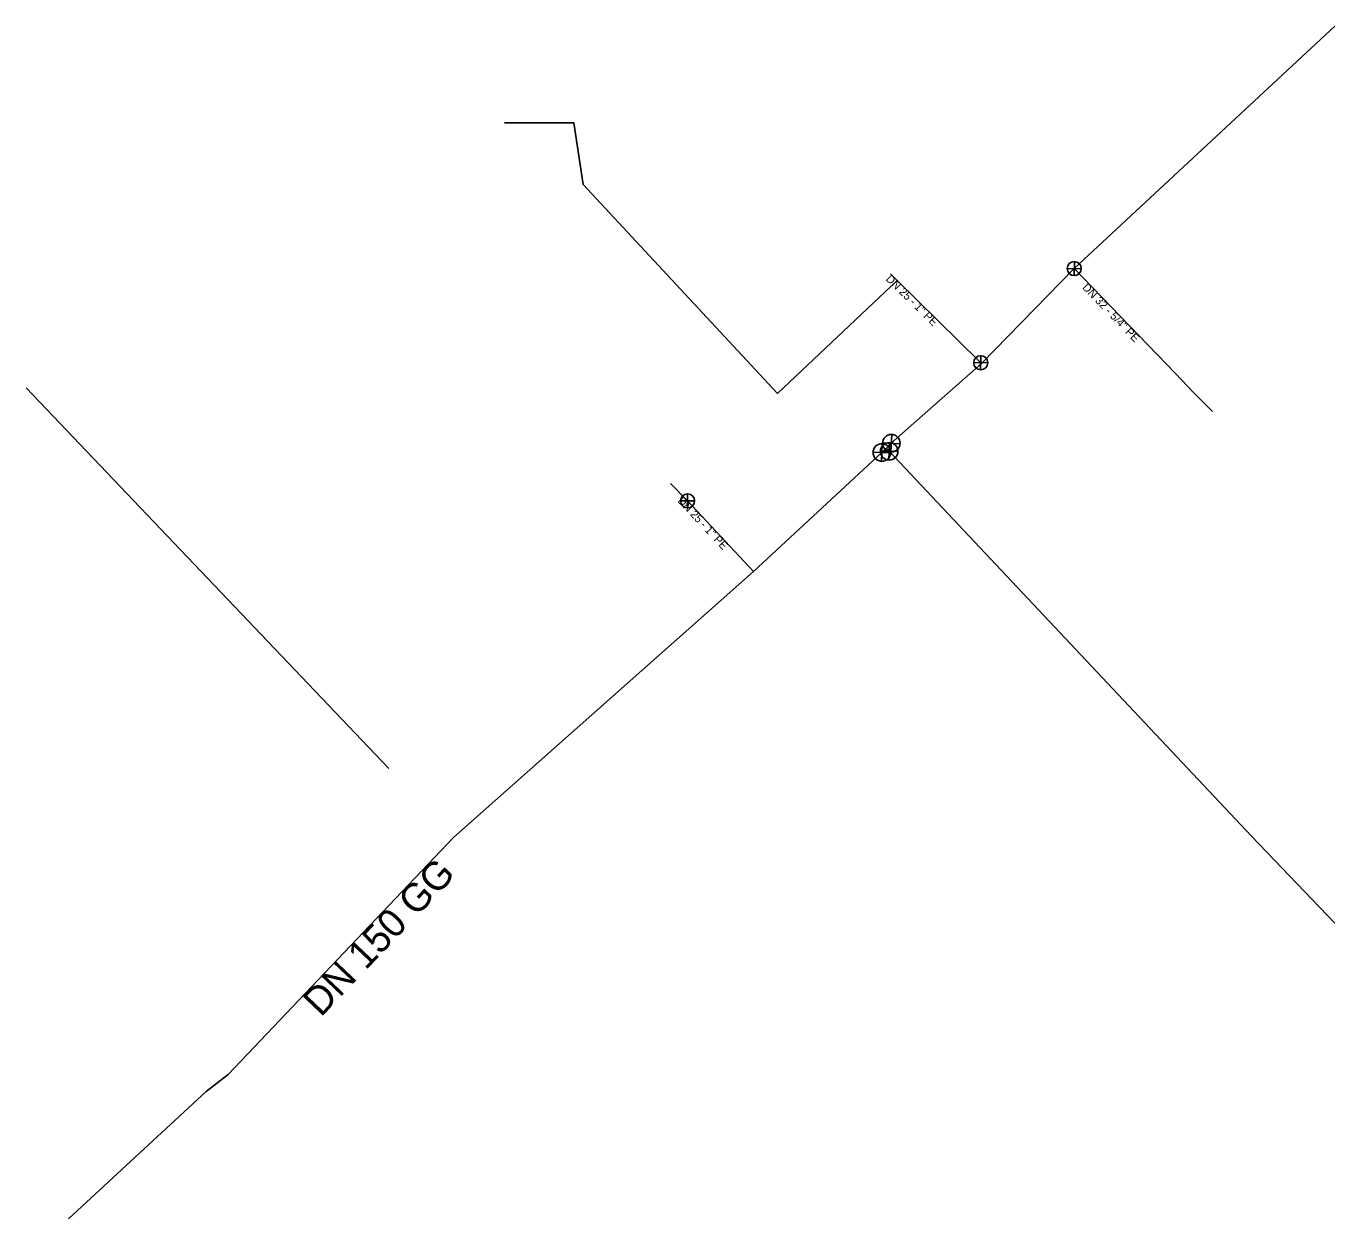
# Model space of a CAD drawing. Extents: x -446989 to -446811, y -1113341 to -1113211.
# Drawn here: x -446885.6 to -446811.2, y -1113340.6 to -1113272.8 of the extents above; entities that cross this region are included whole.
import ezdxf

# ---------------------------------------------------------------- set-up
doc = ezdxf.new("R2010")
doc.units = 0
for name, color, linetype in [('_pripojka_prevzato_z_dokumentace_', 7, 'Continuous'), ('_pripojka_priblizne_', 7, 'Continuous'), ('_voda_smvak_prevzato_z_dokumentace_', 7, 'Continuous'), ('Default', 7, 'Continuous'), ('MoLevel 27', 7, 'Continuous'), ('MoLevel 32', 7, 'Continuous'), ('MoLevel 46', 7, 'Continuous'), ('MoLevel 53', 7, 'Continuous')]:
    doc.layers.add(name, color=color, linetype=linetype)

# ---------------------------------------------------------------- blocks, each defined once
blk = doc.blocks.new('_uzaver_')
at = {"layer": 'Default'}
for p, q in [((-0.000035, -0.000035), (0.000035, 0.000035)), ((0.000035, -0.000035), (-0.000035, 0.000035))]:
    blk.add_line(p, q, dxfattribs=at)
for radius in [0.00005, 0.0000025]:
    blk.add_circle((0, 0), radius, dxfattribs=at)
blk = doc.blocks.new('_uzaver_pripojka_')
at = {"layer": 'Default'}
for p, q in [((-0.000035, -0.000035), (0.000035, 0.000035)), ((0.000035, -0.000035), (-0.000035, 0.000035))]:
    blk.add_line(p, q, dxfattribs=at)
for radius in [0.00005, 0.0000025]:
    blk.add_circle((0, 0), radius, dxfattribs=at)

msp = doc.modelspace()

# ---------------------------------------------------------------- linework, layer by layer
at = {"layer": '_pripojka_prevzato_z_dokumentace_'}
msp.add_line((-446885.588, -1113293.397), (-446864.96, -1113315.053), dxfattribs=at)
at = {"layer": '_pripojka_priblizne_'}
for p, q in [((-446836.061, -1113287.299), (-446836.448, -1113286.919)), ((-446825.999, -1113286.62), (-446820.245, -1113292.595))]:
    msp.add_line(p, q, dxfattribs=at)
for points in [[(-446836.061, -1113287.299), (-446842.877, -1113293.719), (-446853.91, -1113281.839), (-446854.442, -1113278.34), (-446858.398, -1113278.325)], [(-446831.28, -1113292.01), (-446831.4, -1113291.88), (-446836.061, -1113287.299)], [(-446820.246, -1113292.595), (-446819.22, -1113293.66), (-446818.128, -1113294.752)], [(-446848.947, -1113298.846), (-446847.98, -1113299.83), (-446844.23, -1113303.85)]]:
    msp.add_lwpolyline(points, dxfattribs=at)
at = {"layer": '_voda_smvak_prevzato_z_dokumentace_'}
for p, q in [((-446836.674, -1113296.822), (-446836.4, -1113296.55)), ((-446836.94, -1113297.08), (-446836.674, -1113296.822)), ((-446836.52, -1113297.01), (-446836.674, -1113296.822))]:
    msp.add_line(p, q, dxfattribs=at)
for points in [[(-446836.4, -1113296.55), (-446831.28, -1113292.01), (-446826, -1113286.62), (-446811.182, -1113272.838)], [(-446883.181, -1113340.649), (-446875.35, -1113333.4), (-446874.11, -1113332.44), (-446861.3, -1113318.97), (-446859.78, -1113317.62), (-446844.23, -1113303.85), (-446836.94, -1113297.08)], [(-446811.182, -1113323.839), (-446815.92, -1113318.89), (-446836.52, -1113297.01)]]:
    msp.add_lwpolyline(points, dxfattribs=at)

# ---------------------------------------------------------------- block references
at = {"layer": 'MoLevel 27'}
for p, xscale, yscale, rotation in [((-446836.4, -1113296.55), 10000, 10000, 41.580682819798), ((-446836.94, -1113297.08), 10000.000000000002, 10000.000000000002, -137.12581353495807), ((-446836.52, -1113297.01), 10000, 10000, -46.696699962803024)]:
    msp.add_blockref('_uzaver_', p, dxfattribs=dict(at, xscale=xscale, yscale=yscale, rotation=rotation))
at = {"layer": 'MoLevel 53'}
for p, xscale, yscale, rotation in [((-446825.999, -1113286.62), 7999.999999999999, 8000, -46.07945000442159), ((-446831.315, -1113291.973), 7999.999999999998, 8000, 42.9567313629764), ((-446847.98, -1113299.83), 7999.999999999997, 7999.999999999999, 135.27678905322)]:
    msp.add_blockref('_uzaver_pripojka_', p, dxfattribs=dict(at, xscale=xscale, yscale=yscale, rotation=rotation))

# ---------------------------------------------------------------- texts
at = {"layer": 'MoLevel 32'}
for s, rotation, p in [("DN 25 - 1'' PE", 315.50018, (-446836.742, -1113287.251)), ("DN 32 - 5/4'' PE", 313.92056, (-446825.569, -1113287.724)), ("DN 25 - 1'' PE", 313.00983, (-446848.579, -1113299.855))]:
    msp.add_text(s, height=0.455, rotation=rotation, dxfattribs=at).set_placement(p)
at = {"layer": 'MoLevel 46'}
msp.add_text('DN 150 GG', height=1.6049, rotation=46.43863, dxfattribs=at).set_placement((-446868.835, -1113329.222))

doc.saveas('drawing.dxf')
